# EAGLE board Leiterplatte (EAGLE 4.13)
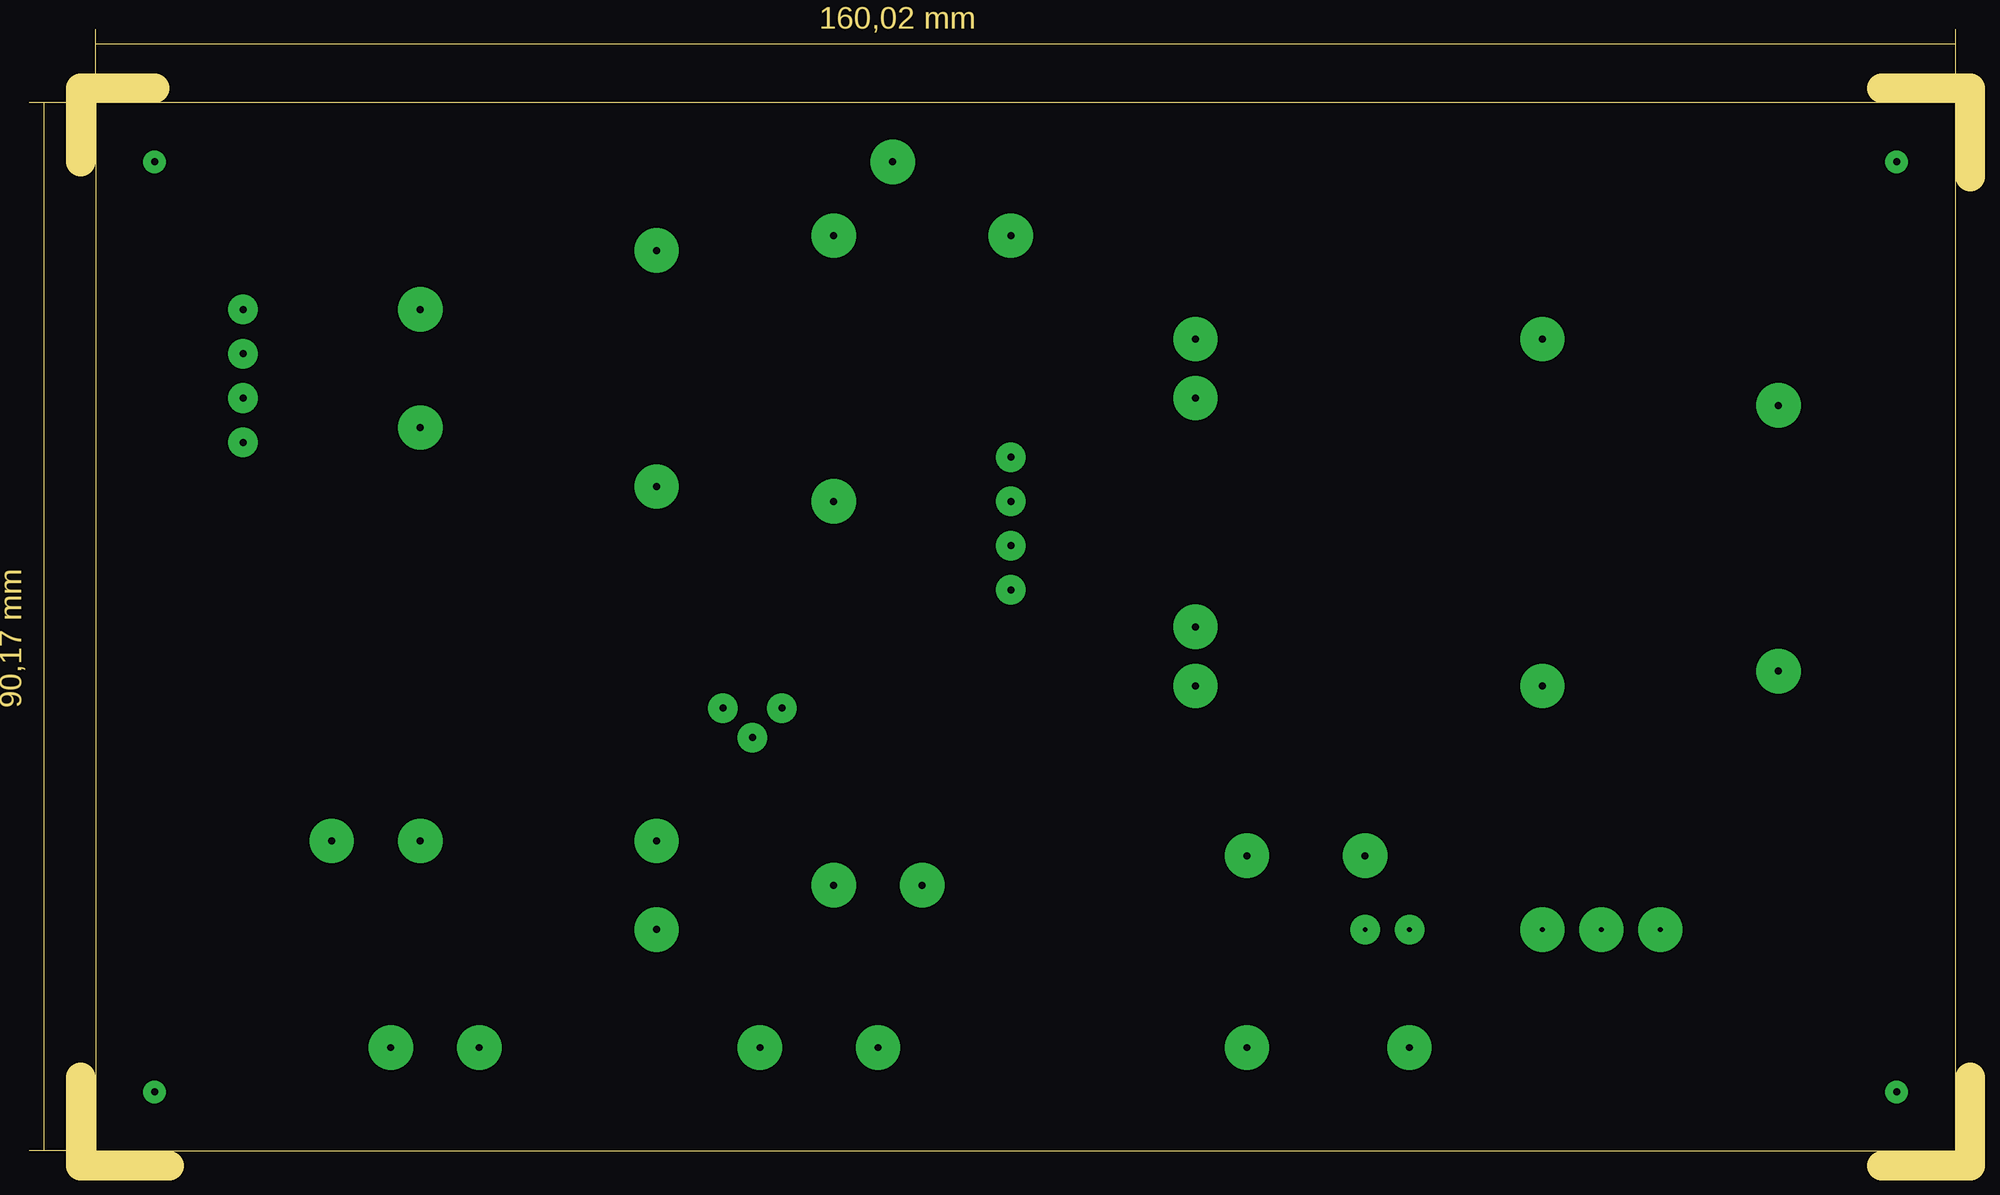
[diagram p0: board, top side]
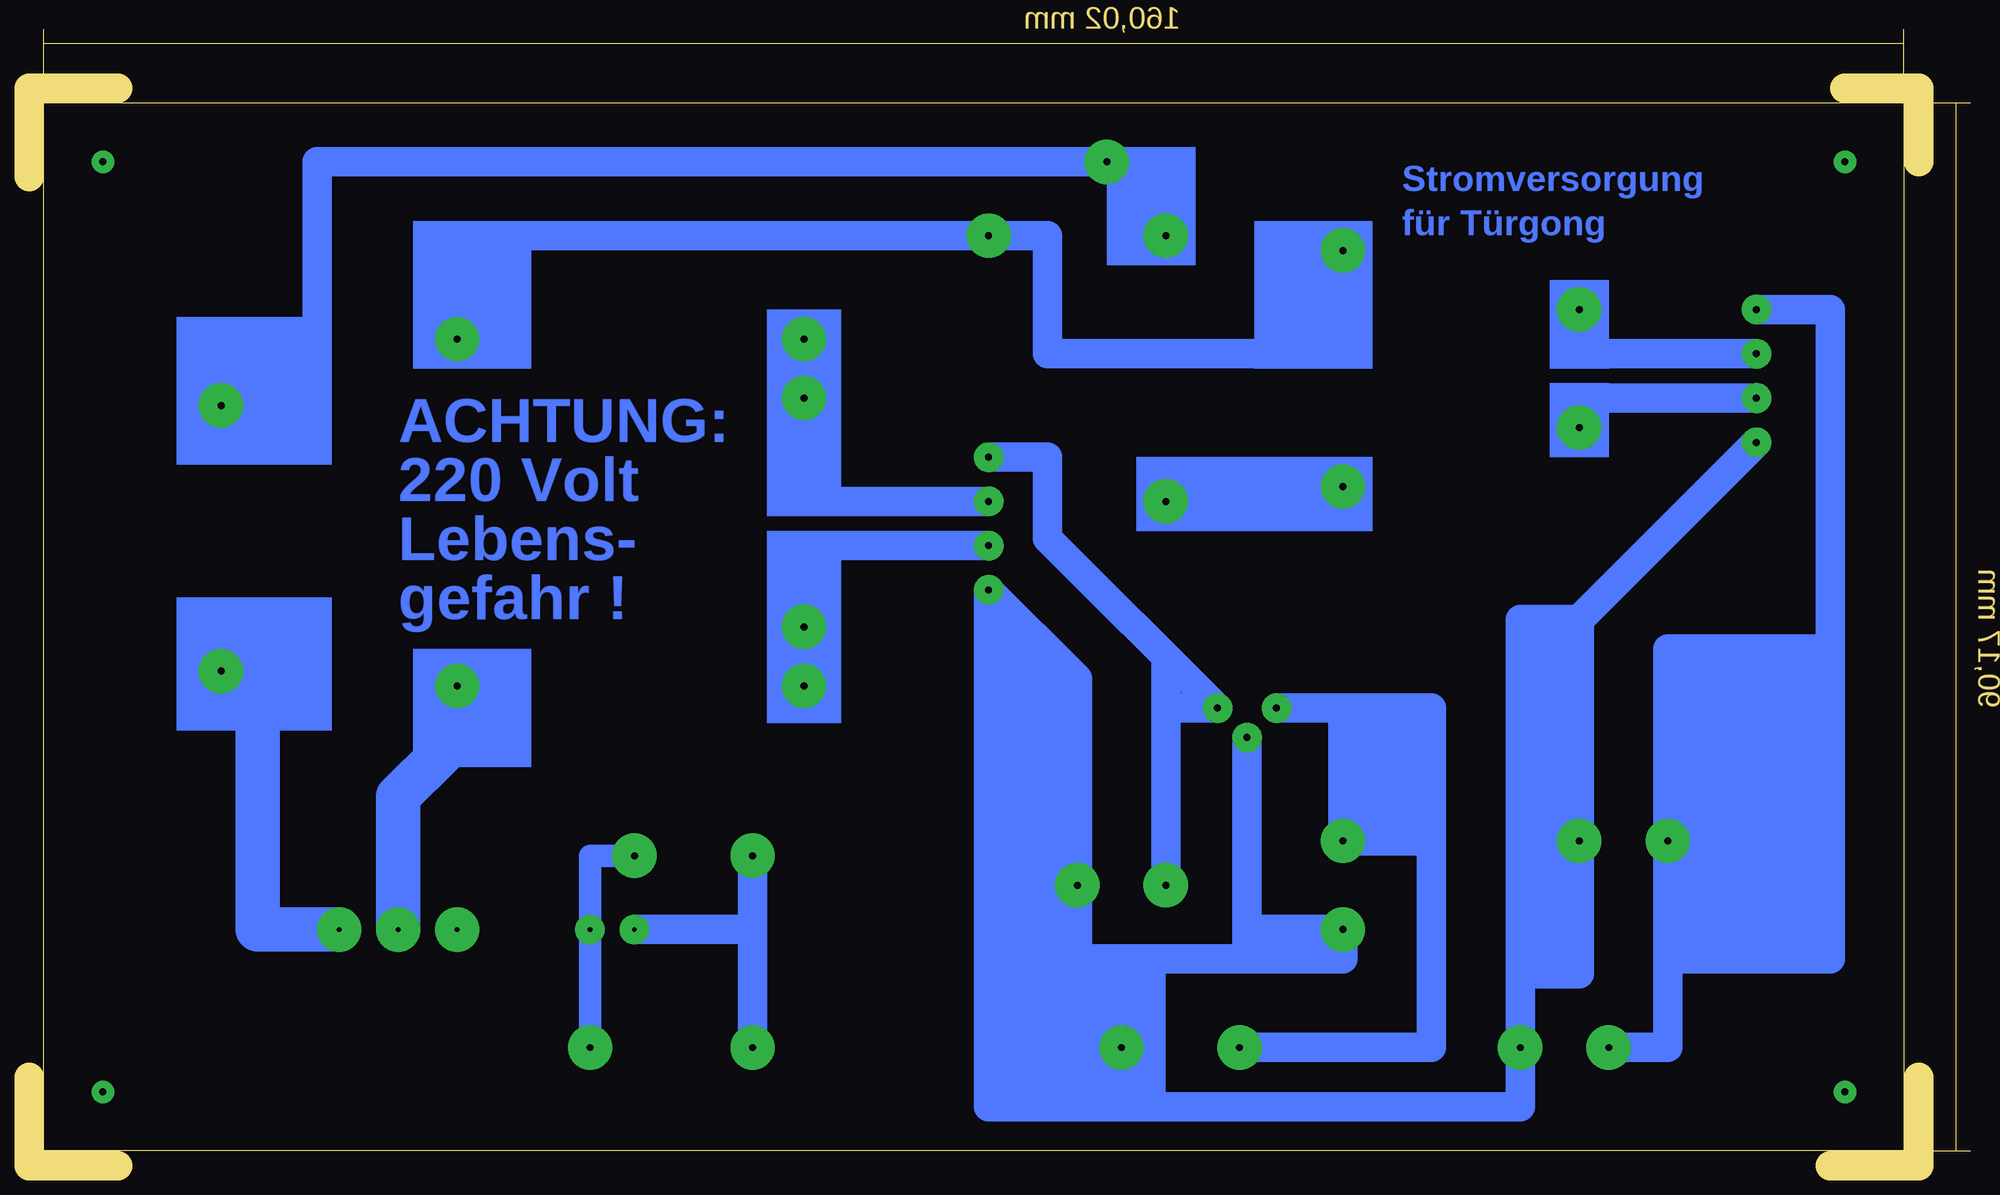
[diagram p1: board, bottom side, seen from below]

Size 167 x 97.79 mm. Coordinates in mm from the lower left corner, seen from the top.
Outline: 165.74,91.44 165.74,1.27 5.71,1.27 5.71,91.44
Outline: 165.74,91.44 5.71,91.44
Outline: 10.79,92.71 4.45,92.71 4.45,86.36
Outline: 159.38,92.71 167,92.71 167,85.09
Outline: 4.45,7.62 4.45,0 12.06,0
Outline: 159.38,0 167,0 167,7.62
Outline: 5.71,91.44 5.71,96.52
Outline: 5.71,96.52 5.71,97.79
Outline: 165.74,91.44 165.74,96.52
Outline: 165.74,96.52 165.74,97.79
Outline: 5.71,96.52 165.74,96.52
Outline: 5.08,91.44 1.27,91.44
Outline: 1.27,91.44 0,91.44
Outline: 5.08,1.27 1.27,1.27
Outline: 1.27,1.27 0,1.27
Outline: 1.27,91.44 1.27,1.27
Copper layers (1*16): Top 0.035mm / dielectric 1.5mm / Bottom 0.035mm
Design rules "default": minimum track width 10mil, minimum drill 24mil, track to track 8mil, track to pad 8mil, pad to pad 8mil, via to via 8mil, smd to smd 8mil, copper to edge 40mil, drill to drill 8mil, minimum pad ring 10mil, minimum via ring 8mil, stop-mask expansion 4mil, vias tented up to drill 0mil, thermal gap 10mil

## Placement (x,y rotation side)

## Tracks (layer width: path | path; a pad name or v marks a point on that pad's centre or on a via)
S$1  (via drill 0.6 pad 1.93)
  other vias: 10.79,6.35
S$2  (via drill 0.6 pad 1.93)
  other vias: 10.79,86.36
S$3  (via drill 0.6 pad 1.93)
  other vias: 160.66,6.35
S$4  (via drill 0.6 pad 1.93)
  other vias: 160.66,86.36
S$5  (via drill 0.4 pad 3.81)
  Bottom 3.81: v140.34,20.32 147.32,20.32 147.32,38.1
S$6  (via drill 0.6 pad 3.81)
  Bottom 3.81: 142.88,42.55 v150.5,42.55
S$7  (via drill 0.6 pad 3.81)
  other vias: 150.5,65.41
S$8  (via drill 0.6 pad 3.81)
  other vias: 130.17,41.28
S$9  (via drill 0.6 pad 3.81)
  other vias: 100.33,71.12
S$10  (via drill 0.6 pad 3.81)
  other vias: 100.33,41.28
S$11  (via drill 0.6 pad 3.81)
  other vias: 118.75,10.16 104.78,10.16
S$13  (via drill 0.6 pad 2.54, 0.6 pad 3.81)
  Bottom 2.54: v84.45,60.96 79.38,60.96 79.38,53.98 v64.77,39.37 69.22,39.37 | v69.22,24.13 69.22,33.02 | 69.22,39.37 69.22,41.28 | 69.22,41.28 69.22,43.18 | 69.22,39.37 69.22,33.02 | 69.22,33.02 69.22,41.28
S$14  (via drill 0.6 pad 2.54, 0.6 pad 3.81)
  Bottom 2.54: v84.45,57.15 100.33,57.15 v100.33,66.04
S$15  (via drill 0.6 pad 2.54, 0.6 pad 3.81)
  Bottom 2.54: v84.45,53.34 100.33,53.34 v100.33,46.36
S$19  (via drill 0.6 pad 3.81)
  Bottom 3.81: v53.97,58.42 67.94,58.42 v69.22,57.15
S$20  (via drill 0.6 pad 3.81)
  Bottom 2.54: v53.97,78.74 53.97,69.85 79.38,69.85 79.38,80.01 v84.45,80.01 130.17,80.01 v130.17,71.12
S$23  (via drill 0.6 pad 2.54, 0.6 pad 3.81)
  Bottom 2.54: v18.41,73.66 12.06,73.66 12.06,44.45 | 12.06,44.45 12.06,27.94 | v31.11,10.16 26.04,10.16 26.04,17.78 | 26.04,17.78 v26.04,27.94 | v26.04,27.94 12.06,27.94 | 12.06,27.94 12.06,17.78 26.04,17.78 | 12.06,44.45 26.04,44.45 v26.04,27.94
S$25  (via drill 0.6 pad 2.54, 0.6 pad 3.81)
  Bottom 2.54: v18.41,69.85 33.66,69.85 v33.66,73.66
S$26  (via drill 0.6 pad 2.54, 0.6 pad 3.81)
  Bottom 2.54: v18.41,66.04 33.66,66.04 v33.66,63.5
S$27  (via drill 0.6 pad 2.54, 0.6 pad 3.81)
  Bottom 2.54: v18.41,62.23 33.66,46.99 | 38.73,27.94 v33.66,27.94 33.66,46.99 | 38.73,27.94 38.73,16.51 | 38.73,16.51 v38.73,10.16 38.73,5.08 70.48,5.08 | 38.73,16.51 33.66,16.51 33.66,27.3 | v62.23,36.83 62.23,20.32 | 62.23,17.78 70.48,17.78 | 70.48,17.78 76.84,17.78 | 76.84,39.37 76.84,41.91 v84.45,49.53 84.45,5.08 76.84,5.08 | 76.84,39.37 v76.84,24.13 76.84,17.78 | 76.84,17.78 76.84,10.16 | 70.48,10.16 70.48,17.78 | v53.97,20.32 54.61,20.32 | 54.61,20.32 62.23,20.32 | 62.23,20.32 62.23,17.78 | 62.23,17.78 53.97,17.78 53.97,19.68 54.61,19.68 54.61,20.32 | 54.61,20.32 60.96,20.32 60.96,19.05 | 70.48,10.16 76.84,10.16 | 76.84,10.16 76.84,5.08 | 76.84,5.08 70.48,5.08 | 70.48,5.08 70.48,10.16 | 76.84,5.08 76.84,39.37 | 76.84,39.37 83.82,46.99 83.82,44.45 77.47,37.47 77.47,35.56 83.82,41.91 | 33.66,46.99 38.73,46.99 38.73,27.94
S$28  (via drill 0.6 pad 3.81)
  Bottom 2.54: v69.22,80.01 69.22,86.36 v74.3,86.36 142.24,86.36 142.24,72.39
S$36  (via drill 0.6 pad 2.54, 0.6 pad 3.81)
  Bottom 2.54: 46.36,27.94 v53.97,27.94 53.97,39.37 | 46.36,27.94 46.36,10.16 v62.86,10.16 | 46.36,27.94 46.36,39.37 53.97,39.37 | v59.69,39.37 53.97,39.37
S$40  (via drill 0.6 pad 3.81)
  other vias: 73.03,10.16
S$42  (via drill 0.4 pad 3.81)
  Bottom 3.81: v135.25,20.32 135.25,31.75 131.44,35.56
S$43  (via drill 0.4 pad 3.81)
  other vias: 130.17,20.32
S$47  (via drill 0.4 pad 2.54, 0.6 pad 3.81)
  Bottom 2.54: 104.78,20.32 v114.94,20.32 | 104.78,20.32 v104.78,26.67 | 104.78,10.16 104.78,20.32
S$49  (via drill 0.4 pad 2.54, 0.6 pad 3.81)
  Bottom 1.93: v114.94,26.67 118.75,26.67 v118.75,20.32 118.75,10.16
(copper drawn outside any net)
  shapes: Bottom area x18

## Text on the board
Bottom: Stromversorgung | für Türgong | ACHTUNG: | 220 Volt | Lebens- | gefahr !
Dimension: 160,02 mm | 90,17 mm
